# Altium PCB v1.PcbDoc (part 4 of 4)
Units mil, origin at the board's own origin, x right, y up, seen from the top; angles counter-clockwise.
Board outline 4875 x 2022 mil, 4 copper layers (Top Layer, Signal Layer 1, Signal Layer 2, Bottom Layer), stack 64.834 mil thick; 432 components, 288 nets, 1177 pads, 637 vias.
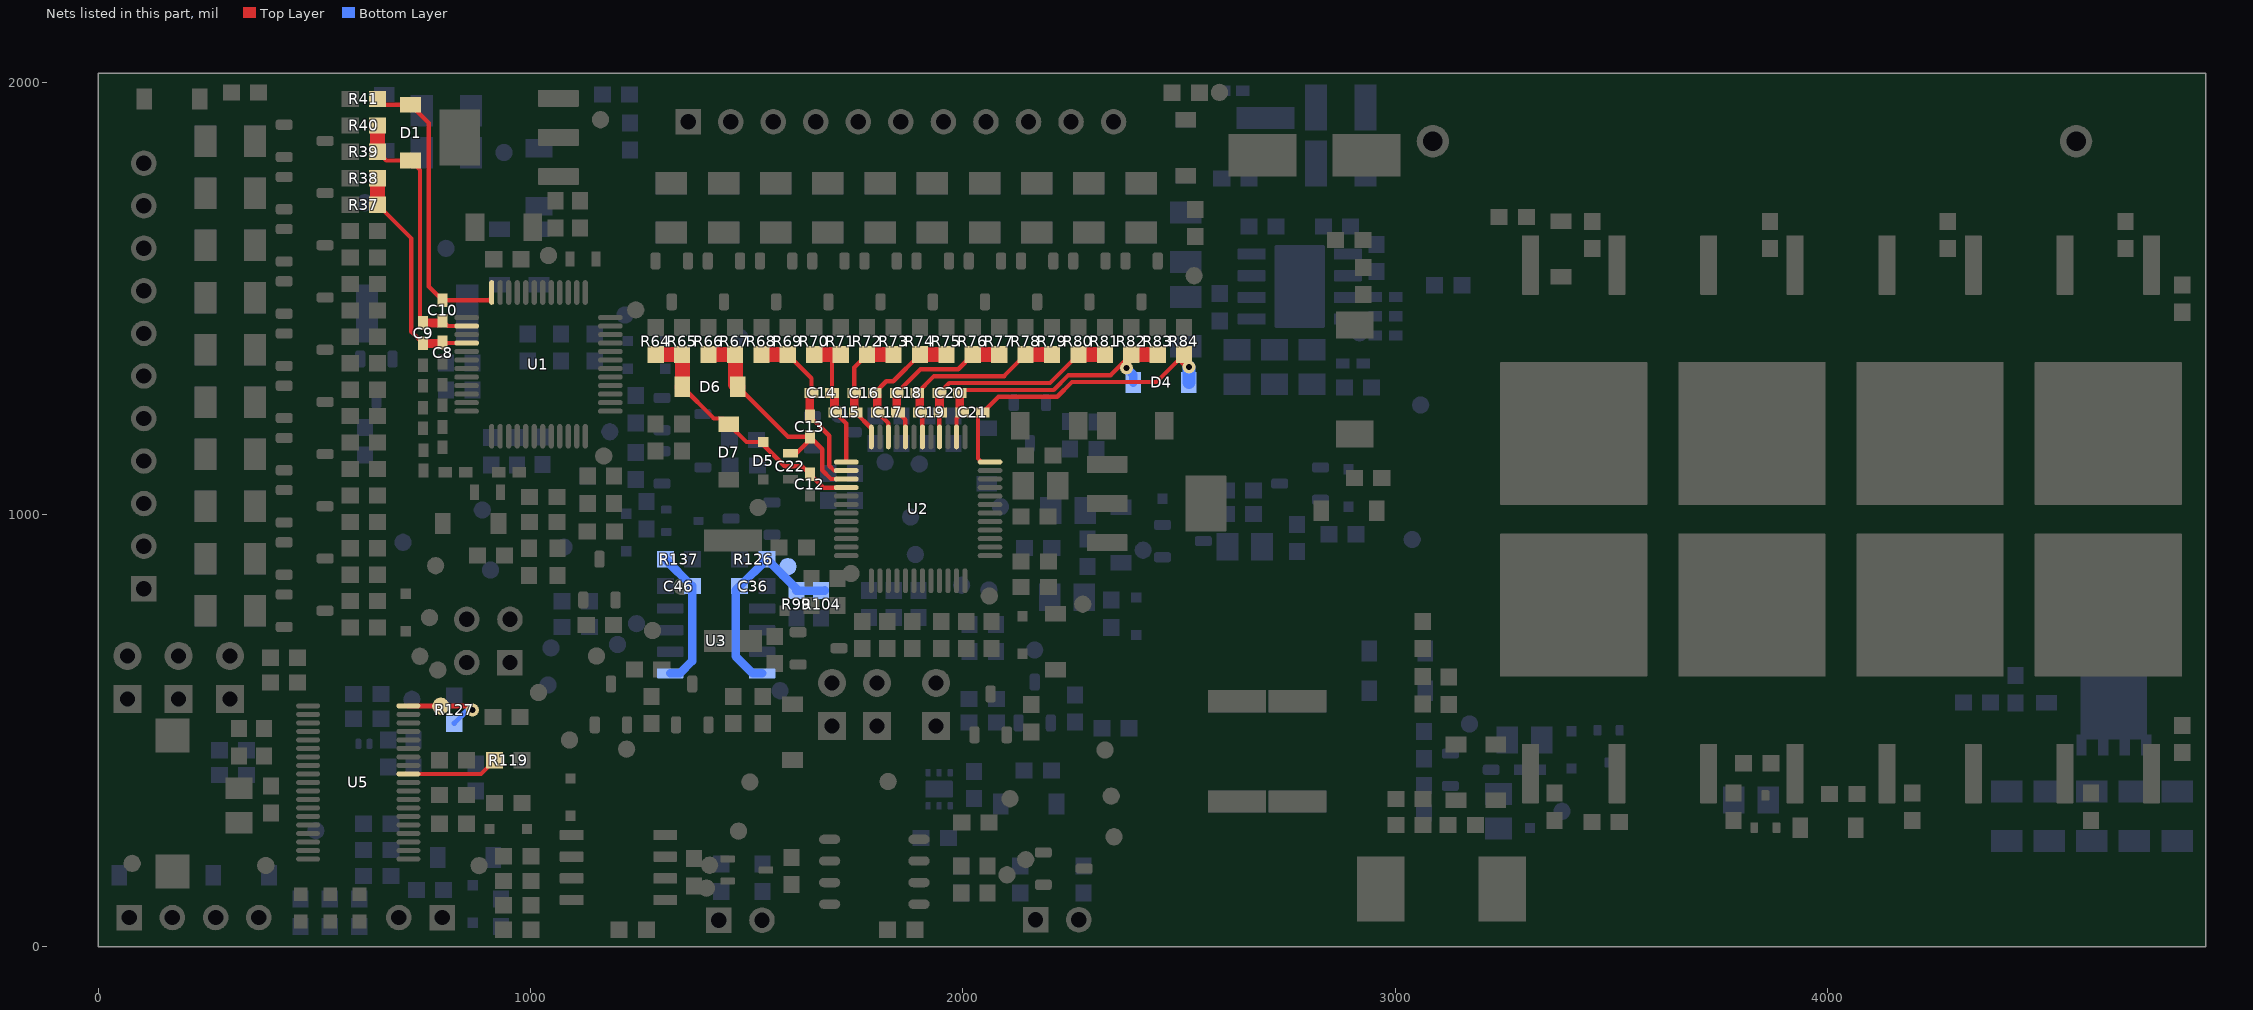
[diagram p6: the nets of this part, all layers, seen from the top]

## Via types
v1: diameter 30, hole 14, Top Layer to Bottom Layer, 615 vias
v2: diameter 19.68, hole 7.87, Top Layer to Bottom Layer, 18 vias
v3: diameter 19.68, hole 7.87, Top Layer to Bottom Layer, tented both sides, 4 vias

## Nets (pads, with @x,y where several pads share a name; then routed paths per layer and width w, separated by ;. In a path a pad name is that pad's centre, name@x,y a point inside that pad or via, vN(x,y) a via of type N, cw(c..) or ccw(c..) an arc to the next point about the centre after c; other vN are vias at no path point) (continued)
VC8: C8.1 C9.2 R37.2 R38.2 U1.4 | length 528.1
  Top Layer w10: R37.2@645.5,1717.52 724,1639.02 724,1423.38 C9.2@751,1396.38 ; C8.1@796,1398.5 797.28,1397.21 U1.4@851.66,1397.21
  Top Layer w20: C9.2@751,1396.38 793.88,1396.38 C8.1@796,1398.5
  Top Layer w35: R37.2@645.5,1717.4 645.5,1717.52 R38.2@645.5,1778.55
VC9: C9.1 C10.2 D1.2 R39.2 R40.2 U1.2 | length 642
  Top Layer w10: R39.2@645.5,1839.7 665.66,1819.53 D1.2@722,1819.53 744,1797.53 744,1450.62 C9.1@751,1443.62 ; C10.2@796,1449 808.42,1436.58 U1.2@851.66,1436.58
  Top Layer w20: C9.1@751,1443.62 790.62,1443.62 C10.2@796,1449
  Top Layer w35: R39.2@645.5,1839.7 R40.2@645.5,1900.85
VC10: C10.1 D1.1 R41.2 U1.48 | length 693
  Top Layer w10: R41.2@645.5,1962 659.03,1948.47 D1.1@722,1948.47 764,1906.47 764,1528.24 C10.1@796,1496.24 903.24,1496.24 909.73,1502.73 U1.48@909.73,1514.34
VC10B: C12.1 D5.1 D6.2 D7.1 R64.2 R65.2 U2.16 | length 615.7
  Top Layer w10: D6.2@1350.53,1296 1423.83,1222.7 1444.77,1222.7 D7.1@1458,1209.47 1499.16,1168.31 D5.1@1538,1168.31 1538,1161.94 1587.94,1112 1627.62,1112 C12.1@1646,1093.62 1676.78,1062.84 U2.16@1730.04,1062.84
  Top Layer w35: R64.2@1289.27,1370.5 R65.2@1350.39,1370.5 ; D6.2@1350.53,1296 1351.06,1296.53 R65.2@1351.06,1370.5
VC11: C13.2 C22.1 D6.1 R66.2 R67.2 U2.15 | length 570.8
  Top Layer w10: D6.1@1479.47,1296 1595.09,1180.38 C13.2@1645.88,1180.38 ; C22.1@1601,1142 1614.33,1142 1645.88,1173.55 C13.2@1645.88,1180.38 ; U2.15@1730.04,1082.53 1694.97,1082.53 1674.5,1103 1674.5,1151.76 C13.2@1645.88,1180.38
  Top Layer w35: R66.2@1411.52,1370.5 R67.2@1472.64,1370.5 1474,1369.15 1474,1301.47 D6.1@1479.47,1296
VC12: C13.1 C14.2 R68.2 R69.2 U2.14 | length 405.1
  Top Layer w10: R69.2@1594.9,1370.5 1649.76,1315.64 C14.2@1649.76,1282 ; C13.1@1645.88,1227.62 1690.5,1183 1690.5,1113.47 1701.75,1102.21 U2.14@1730.04,1102.21
  Top Layer w20: C13.1@1646,1227.62 1646,1278.24 C14.2@1649.76,1282
  Top Layer w35: R68.2@1533.77,1370.5 R69.2@1594.9,1370.5
VC13: C14.1 C15.2 R70.2 R71.2 U2.13 | length 303.3
  Top Layer w10: C14.1@1697,1282 1697,1370.5 ; C15.2@1704.38,1236.7 1730.04,1211.04 U2.13@1730.04,1121.9
  Top Layer w20: C14.1@1697,1282 1702.76,1276.24 1702.76,1238.32 C15.2@1704.38,1236.7
  Top Layer w35: R70.2@1656.02,1370.5 1697,1370.5
VC14: C15.1 C16.2 R72.2 R73.2 U2.12 | length 280.5
  Top Layer w10: C16.2@1748.42,1282 1748.42,1340.65 R72.2@1778.28,1370.5 ; C15.1@1751.62,1236.7 1788.11,1200.21 U2.12@1788.11,1179.97
  Top Layer w20: C16.2@1748.42,1282 1748.42,1239.9 C15.1@1751.62,1236.7
  Top Layer w35: R72.2@1778.28,1370.5 R73.2@1839.4,1370.5
VC15: C16.1 C17.2 R74.2 R75.2 U2.10 | length 317.9
  Top Layer w10: C16.1@1795.67,1282 1822.67,1309 1839.02,1309 R74.2@1900.53,1370.5 ; C17.2@1802.5,1236.7 1827.48,1211.72 U2.10@1827.48,1179.97
  Top Layer w20: C16.1@1795.67,1282 1801.59,1276.08 1801.59,1237.62 C17.2@1802.5,1236.7
  Top Layer w35: R74.2@1900.53,1370.5 R75.2@1961.65,1370.5
VC16: C17.1 C18.2 R76.2 R77.2 U2.8 | length 383.7
  Top Layer w10: C18.2@1847.09,1282 1901.9,1336.81 1989.09,1336.81 R76.2@2022.78,1370.5 ; C17.1@1849.75,1236.7 1866.85,1219.6 U2.8@1866.85,1179.97
  Top Layer w20: C18.2@1847.09,1282 1847.09,1239.36 C17.1@1849.75,1236.7
  Top Layer w35: R76.2@2022.78,1370.5 R77.2@2083.91,1370.5
VC17: C18.1 C19.2 R78.2 R79.2 U2.6 | length 455.4
  Top Layer w10: C18.1@1894.33,1282 1933.14,1320.81 2095.34,1320.81 R78.2@2145.03,1370.5 ; C19.2@1900.63,1236.7 1906.22,1231.11 U2.6@1906.22,1179.97
  Top Layer w20: C18.1@1894.33,1282 1900,1276.33 1900,1237.33 C19.2@1900.63,1236.7
  Top Layer w35: R78.2@2145.03,1370.5 R79.2@2206.16,1370.5
VC18: C19.1 C20.2 R80.2 R81.2 U2.4 | length 523.2
  Top Layer w10: U2.4@1945.59,1179.97 1945.59,1234.42 C19.1@1947.87,1236.7 ; C20.2@1945.76,1282 1968.57,1304.81 2201.59,1304.81 R80.2@2267.29,1370.5
  Top Layer w20: C20.2@1945.76,1282 1945.76,1238.82 C19.1@1947.87,1236.7
  Top Layer w35: R80.2@2267.29,1370.5 R81.2@2328.41,1370.5
VC19: C20.1 C21.2 D4.2 R82.2 R83.2 U2.2 | length 649.1
  Top Layer w10: U2.2@1984.96,1179.97 1984.96,1222.91 C21.2@1998.76,1236.7 ; C20.1@1993,1282 1993,1288.81 2210.03,1288.81 2244.22,1323 2342.03,1323 R82.2@2389.54,1370.5
  Top Layer w20: C20.1@1993,1282 1993,1242.46 C21.2@1998.76,1236.7
  Top Layer w35: R82.2@2389.54,1370.5 R83.2@2450.66,1370.5
  Bottom Layer w20: v1(2378,1340) 2394,1324 D4.2@2394,1306
VC20: C21.1 D4.1 R84.2 U2.48 | length 732.7
  Top Layer w10: U2.48@2062.72,1121.9 2043.1,1121.9 2035,1130 2035,1225.7 C21.1@2046,1236.7 2082.11,1272.81 2218.14,1272.81 2252.33,1307 2447.76,1307 R84.2@2511.27,1370.5
  Top Layer w20: R84.2@2511.27,1370.5 2511.27,1354.07 v1(2523.33,1342)
  Bottom Layer w30: D4.1@2522.94,1306 2523.33,1306.39 v1(2523.33,1342)
VCC1: C36.1 pad.1@1595,880 R99.2 R104.2 R126.2 U3.8 | length 498.8
  Bottom Layer w20: U3.8@1535.3,633 1513.46,633 1474,672.46 1474,825.43 C36.1@1483.5,834.93 1484.36,834.93 R126.2@1546.5,897.07 1615,828.56 R99.2@1615,824.5 R104.2@1672,824.5 1679.73,824.5 R104.2@1680,824.76
VCC1_C: R119.1 U5.30 | length 212.5
  Top Layer w10: U5.30@717.14,400.33 884.84,400.33 R119.1@916.5,432
VCC2: C46.1 R137.2 U3.1 | length 323.6
  Bottom Layer w20: R137.2@1311.5,897 1373.36,835.14 1373.36,661.42 1344.94,633 U3.1@1322.7,633
VCC2_C: pad.1@792,557 R127.1 U5.38 | length 206.6
  Top Layer w12: U5.38@717.14,557.81 855.19,557.81 v1(865,548)
  Bottom Layer w12: R127.1@823,517.5 853.5,548 v1(865,548)
pads on no net: RT7.1S RT7.2S U1.1 U1.3 U1.5 U1.7 U1.9 U1.11 U1.19 U1.39 U1.40 U1.43 U1.44 U1.45 U2.1 U2.3 U2.5 U2.7 U2.9 U2.11 U2.19 U2.40 U2.44 U4.7@1927.28,365 U4.7@1962.72,365 U5.2 U5.6 U5.12 U5.32 U5.33 U5.37 U9.6 U9.9@2779.33,1528

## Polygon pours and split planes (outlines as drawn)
NetD19_1 on Top Layer "TOP_LAYER_NETD19_1_P269" (solid, remove dead copper, pour order 269): 3046,1498 3046,512 4852,512 4852,1418.43 4211.07,1418.43 4131.5,1498
Current+ on Top Layer "TOP_LAYER_CURRENT+_P268" (solid, remove dead copper, pour order 268): 2427,488 3022,488 3022,865 2427,865
UP_GND on Top Layer "TOP_LAYER_UP_GND_P244" (solid, remove dead copper, pour order 244): 1196,2008 1196,1570 1275,1491 1275,1329 1332,1272 1401,1203 1401,619.89 1646.2,619.89 1646.2,478 1974,478 1974,616 2252.33,616 2252.33,1146.47 2381,1146.47 2381,1268 2567,1268 2567,2008
GND on Top Layer "TOP_LAYER_GND_P242" (solid, remove dead copper, pour order 242): 30,2008 30,17 2409.97,17 2409.97,885 3013,885 3013,2007 2577,2007 2577,1038 2270,1038 2270,605 1979.12,605 1979.12,463 1636,463 1636,599 1384,599 1384,1210 1264,1330 1264,1486 1186,1564 1186,2008
NetC57_2 on Top Layer "TOP_LAYER_NETC57_2_P218" (solid, remove dead copper, pour order 218): 4157,2008 3046,2008 3046,1508 4136.04,1508 4217.04,1427 4853,1427 4853,1675 4212,1675 cw(c4212,1730) 4157,1730
TOP_REG2 on Top Layer "TOP_LAYER_TOP_REG2_P190" (solid, remove dead copper, pour order 190): 1394,874.88 1528,874.88 1528,675 1394,675
NetC44_1 on Top Layer "TOP_LAYER_NETC44_1_P188" (solid, remove dead copper, pour order 188): 780,2007 998,2007 998,1944 ccw(c1016,1944) 1016,1926 1105,1926 1132,1899 1132,1820 1017,1820 ccw(c1017,1804) 1001,1804 1001,1743 780,1743
NetQ40_5 on Top Layer "TOP_LAYER_NETQ40_5_P082" (solid, remove dead copper, pour order 82): 4792,492 4792,532 cw(c4802,532) 4802,542 4833,542 4833,615 4573,615 4573,492
BAT+ on Top Layer "TOP_LAYER_BAT+_P076" (solid, remove dead copper, pour order 76): 4196,1717 4196,2008 4860,2008 4860,1717
PACK+ on Top Layer "TOP_LAYER_PACK+_P072" (solid, remove dead copper, pour order 72): 4860,17 3046,17 3046,473 4860,473
UP_GND on Bottom Layer "BOTTOM_LAYER_UP_GND_P260" (solid, remove dead copper, pour order 260): 1196,2008 1196,1570 1275,1491 1275,1329 1332,1272 1401,1203 1401,619.89 1646.2,619.89 1646.2,478 1974,478 1974,616 2248,616 2248,1063 2381,1063 2381,1268 2567,1268 2567,2008
NetC78_1 on Bottom Layer "BOTTOM_LAYER_NETC78_1_P262" (solid, remove dead copper, pour order 262): 2602.83,1327 2912,1327 2912,1271 2950,1233 2950,1209 2865,1209 2816,1258 2602.83,1258
NetD19_1 on Bottom Layer "BOTTOM_LAYER_NETD19_1_P084" (solid, remove dead copper, pour order 84): 4860,523 3095,523 3095,1496.4 4860,1496.4
NetC45_1 on Bottom Layer "BOTTOM_LAYER_NETC45_1_P266" (solid, remove dead copper, pour order 266): 2565,1416 2565,1364 2494,1364 2494,1277 2525.23,1245.77 2812.74,1245.77 2860,1198.51 2860,1157.4 2493.67,1157.4 2425,1226.07 2425,1416
GND on Bottom Layer "BOTTOM_LAYER_GND_P256" (solid, remove dead copper, pour order 256): 30,2008 30,17 2409.97,17 2409.97,885 3013,885 3013,2007 2577,2007 2577,1038 2270,1038 2270,605 1979.12,605 1979.12,463 1636,463 1636,599 1389,599 1389,1205 1264,1330 1264,1486 1186,1564 1186,2008
NetD11_1 on Bottom Layer "BOTTOM_LAYER_NETD11_1_P254" (solid, remove dead copper, pour order 254): 632,1976 632,1746 775,1746 775,1976
NetC44_1 on Bottom Layer "BOTTOM_LAYER_NETC44_1_P232" (solid, remove dead copper, pour order 232): 784,1976 784,1746 1184,1746 1184,1976
NetC57_2 on Bottom Layer "BOTTOM_LAYER_NETC57_2_P222" (solid, remove dead copper, pour order 222): 4157,2007 4157,1727.23 4157,1563 3046,1563 3046,2007
BAT+ on Bottom Layer "BOTTOM_LAYER_BAT+_P208" (solid, remove dead copper, pour order 208): 4196,1716 4196,2007 4860,2007 4860,1716
NetC77_2 on Bottom Layer "BOTTOM_LAYER_NETC77_2_P092" (solid, remove dead copper, pour order 92): 2857.33,1590 2921.95,1590 2936.95,1605 2975.33,1605 2975.33,1686 2877.33,1686 2877.33,1649 2857.33,1629
NetC72_1 on Bottom Layer "BOTTOM_LAYER_NETC72_1_P090" (solid, remove dead copper, pour order 90): 2631.33,1759 2842.33,1759 2842.33,1865 2631.33,1865
NetC71_1 on Bottom Layer "BOTTOM_LAYER_NETC71_1_P088" (solid, remove dead copper, pour order 88): 2631.33,1995 2842.33,1995 2842.33,1889 2631.33,1889
PACK+ on Bottom Layer "BOTTOM_LAYER_PACK+_P086" (solid, remove dead copper, pour order 86): 4860,275.21 4860,17 3046,17 3046,275.21
NetQ40_5 on Bottom Layer "BOTTOM_LAYER_NETQ40_5_P070" (solid, remove dead copper, pour order 70): 3547,314 3547,533 4531,533 ccw(c4531,547) 4545,547 4545,630 4860,630 4860,314
NetC45_1 on Signal Layer 2 "SIGNAL_LAYER_2_NETC45_1_P252" (solid, remove dead copper, pour order 252): 2392,1063 2689.98,1063 2689.98,1238 2392,1238
UP_GND on Signal Layer 2 "SIGNAL_LAYER_2_UP_GND_P250" (solid, remove dead copper, pour order 250): 1196,2008 1196,1570 1275,1491 1275,1329 1332,1272 1401,1203 1401,619.89 1646.2,619.89 1646.2,478 1974,478 1974,616 2244.8,616 2244.8,1063 2381,1063 2381,1249 2567,1249 2567,2008
GND on Signal Layer 2 "SIGNAL_LAYER_2_GND_P248" (solid, remove dead copper, pour order 248): 30,2008 30,17 2409.97,17 2409.97,885 3013,885 3013,2007 2577,2007 2577,1052 2256,1052 2256,605 1987,605 1987,463 1636,463 1636,599 1389,599 1389,1205 1264,1330 1264,1486 1186,1564 1186,2008
NetC44_1 on Signal Layer 2 "SIGNAL_LAYER_2_NETC44_1_P228" (solid, remove dead copper, pour order 228): 780,2007 780,1743 1132,1743 1132,2007
NetC57_2 on Signal Layer 2 "SIGNAL_LAYER_2_NETC57_2_P220" (solid, remove dead copper, pour order 220): 4157,2007 4157,1727.23 ccw(c4213.98,1731.98) 4218.73,1675 4860,1675 4860,1508 3046,1508 3046,2007
BAT+ on Signal Layer 2 "SIGNAL_LAYER_2_BAT+_P206" (solid, remove dead copper, pour order 206): 4196,1717 4196,2007 4860,2007 4860,1717
NetQ40_5 on Signal Layer 2 "SIGNAL_LAYER_2_NETQ40_5_P202" (solid, remove dead copper, pour order 202): 3046,286 3046,533 4531,533 ccw(c4531,547) 4545,547 4545,630 4860,630 4860,286
PACK+ on Signal Layer 2 "SIGNAL_LAYER_2_PACK+_P198" (solid, remove dead copper, pour order 198): 4860,266 4860,17 3046,17 3046,266 3919,266
NetD19_1 on Signal Layer 2 "SIGNAL_LAYER_2_NETD19_1_P094" (solid, remove dead copper, pour order 94): 4860,530 3046,530 3046,1498 4860,1498
GND on Signal Layer 1 "SIGNAL_LAYER_1_GND_P246" (solid, remove dead copper, pour order 246): 30,2008 30,17 2409.97,17 2409.97,885 3013,885 3013,2007 2577,2007 2577,1052 2256,1052 2256,605 1979.12,605 1979.12,463 1636,463 1636,599 1389,599 1389,1205 1264,1330 1264,1486 1186,1564 1186,2008
UP_GND on Signal Layer 1 "SIGNAL_LAYER_1_UP_GND_P240" (solid, remove dead copper, pour order 240): 1196,2008 1196,1570 1275,1491 1275,1329 1332,1272 1401,1203 1401,619.89 1646.2,619.89 1646.2,478 1974,478 1974,616 2244.8,616 2244.8,1063 2381,1063 2381,1249 2567,1249 2567,2008
NetC45_1 on Signal Layer 1 "SIGNAL_LAYER_1_NETC45_1_P234" (solid, remove dead copper, pour order 234): 2392,1063 2689.98,1063 2689.98,1238 2392,1238
NetC44_1 on Signal Layer 1 "SIGNAL_LAYER_1_NETC44_1_P226" (solid, remove dead copper, pour order 226): 780,2007 780,1743 1132,1743 1132,2007
NetC57_2 on Signal Layer 1 "SIGNAL_LAYER_1_NETC57_2_P210" (solid, remove dead copper, pour order 210): 4157,2007 4157,1727.23 ccw(c4213.98,1731.98) 4218.73,1675 4860,1675 4860,1508 3046,1508 3046,2007
BAT+ on Signal Layer 1 "SIGNAL_LAYER_1_BAT+_P204" (solid, remove dead copper, pour order 204): 4196,1717 4196,2007 4860,2007 4860,1717
NetQ40_5 on Signal Layer 1 "SIGNAL_LAYER_1_NETQ40_5_P200" (solid, remove dead copper, pour order 200): 3046,286 3046,533 4531,533 ccw(c4531,547) 4545,547 4545,630 4860,630 4860,286
PACK+ on Signal Layer 1 "SIGNAL_LAYER_1_PACK+_P196" (solid, remove dead copper, pour order 196): 4860,266 4860,17 3046,17 3046,266
NetD19_1 on Signal Layer 1 "SIGNAL_LAYER_1_NETD19_1_P096" (solid, remove dead copper, pour order 96): 4860,541 3046,541 3046,1498 4860,1498

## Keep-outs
Keep-Out Layer:
  text ".Layer_Name" at 577,-858.49 h60

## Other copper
Top Layer:
  rectangle net PACK-: 2492,17 2897,237
  rectangle net PACK+: 4194,17 4860,194
  region net BAT+: 4860,2008 4606,2008 4606,1717.18 4860,1717.18
  rectangle net Current+: 2476,690 2881,865
  rectangle net CANL: 2080,17 2197,93
  region net CANH: 2356,93 2239,93 2239,17 2356,17
  region net 485B: 1623,92 1506,92 1506,17 1623,17
  rectangle net 485A: 1347,17 1464,92
  region net NetC45_1: 2284,979 2375,979 cw(c2375,955) 2399,955 2399,919.05 2690,919.05 2690,1238 2407,1238 2407,1110 cw(c2370,1110) 2370,1073 2284,1073
  region net NetC73_1: 2590,1881.64 2590,1782.59 2772.2,1782.59 2772.2,1881.64
  region net Cell1: 143,854.19 143,741 315.91,741 315.91,854.19
  region net Cell2: 189,974.94 189,861.84 315.91,861.84 315.91,974.94
  region net Cell3: 169,1095.7 169,982.6 315.91,982.6 315.91,1095.7
  region net Cell4: 150,1216.46 150,1103.35 315.91,1103.35 315.91,1216.46
  region net Cell5: 150,1337.22 150,1224.11 315.91,1224.11 315.91,1337.22
  region net Cell6: 150,1457.98 150,1344.87 315.91,1344.87 315.91,1457.98
  region net Cell7: 150,1578.74 150,1465.63 315.91,1465.63 315.91,1578.74
  region net Cell8: 150,1699.5 150,1586.39 315.91,1586.39 315.91,1699.5
  region net Cell10: 91,1930 91,1827.91 315.91,1827.91 315.91,1930
  region net Cell9: 150,1820.25 150,1707.15 315.91,1707.15 315.91,1820.25
  region net Cell11: 1401.97,1870 1288.86,1870 1288.86,1699.09 1401.97,1699.09
  region net Cell12: 1522.72,1824 1409.62,1824 1409.62,1699.09 1522.72,1699.09
  region net Cell13: 1643.48,1842 1530.38,1842 1530.38,1699.09 1643.48,1699.09
  region net Cell14: 1764.24,1865 1651.13,1865 1651.13,1699.09 1764.24,1699.09
  region net Cell19: 2368.03,1865 2254.93,1865 2254.93,1699.09 2368.03,1699.09
  region net Cell20: 2485,1876 2375.69,1876 2375.69,1699.09 2485,1699.09
  region net Cell18: 2247.28,1865 2134.17,1865 2134.17,1699.09 2247.28,1699.09
  region net Cell17: 2126.52,1865 2013.41,1865 2013.41,1699.09 2126.52,1699.09
  region net Cell16: 2005.76,1865 1892.65,1865 1892.65,1699.09 2005.76,1699.09
  region net Cell15: 1885,1865 1771.89,1865 1771.89,1699.09 1885,1699.09
  region net NetC78_1: 2863,1252 2950.7,1252 2950.7,1155 2863,1155
  region net PACK-: 2427,413 3022,413 3022,17 2427,17
  text ".Layer_Name" at 577,-858.49 h60
Signal Layer 1:
  region net PACK-: 2428,413 3022,413 3022,17 2428,17
  region net Current+: 2428,488 3022,488 3022,865 2428,865
Signal Layer 2:
  region net PACK-: 2428,413 3022,413 3022,17 2428,17
  region net Current+: 2428,488 3022,488 3022,865 2428,865
Bottom Layer:
  rectangle net PACK+: 4194,17 4860,194
  rectangle net PACK-: 2492,17 2897,237
  rectangle net Current+: 2476,690 2884,836
  region net BAT+: 4860,2007 4586,2007 4586,1716 4860,1716
  region net NetR108_2: 2565,1424 2463,1424 2463,1666 2565,1666
  region net NetD12_1: 2463,1881 2565,1881 2565,1674 2463,1674
  region net Cell15: 1845.21,1839 1733.03,1839 1733.03,1699 1845.21,1699
  region net Cell11: 1362.17,1870 1258.59,1870 1258.59,1699 1362.17,1699
  region net Cell12: 1482.93,1816 1370.76,1816 1370.76,1699 1482.93,1699
  region net Cell13: 1603.69,1809 1491.52,1809 1491.52,1699 1603.69,1699
  region net Cell14: 1724.45,1829 1612.28,1829 1612.28,1699 1724.45,1699
  region net Cell16: 1965.97,1864.54 1853.79,1864.54 1853.79,1699 1965.97,1699
  region net Cell17: 2086.72,1875.67 1974.55,1875.67 1974.55,1699 2086.72,1699
  region net Cell18: 2207.48,1876 2095.31,1876 2095.31,1699 2207.48,1699
  region net Cell19: 2328.24,1876 2216.07,1876 2216.07,1699 2328.24,1699
  region net Cell20: 2449,1875.67 2336.83,1875.67 2336.83,1699 2449,1699
  region net NetQ20_3: 2449,1460.31 2336.83,1460.31 2336.83,1679 2449,1679
  region net NetQ19_3: 2328.24,1460.31 2216.07,1460.31 2216.07,1679 2328.24,1679
  region net NetQ18_3: 2207.48,1460.31 2095.31,1460.31 2095.31,1679 2207.48,1679
  region net NetQ17_3: 2086.72,1460.31 1974.55,1460.31 1974.55,1679 2086.72,1679
  region net NetQ16_3: 1965.97,1460.31 1853.79,1460.31 1853.79,1679 1965.97,1679
  region net NetQ15_3: 1845.21,1460.31 1733.03,1460.31 1733.03,1679 1845.21,1679
  region net NetQ14_3: 1724.45,1460.31 1612.28,1460.31 1612.28,1679 1724.45,1679
  region net NetQ13_3: 1603.69,1460.31 1491.52,1460.31 1491.52,1679 1603.69,1679
  region net NetQ12_3: 1482.93,1460.31 1370.76,1460.31 1370.76,1679 1482.93,1679
  region net NetQ11_3: 1362.17,1460.31 1258.59,1460.31 1258.59,1679 1362.17,1679
  region net NetQ1_3: 622,741.03 622,855.03 336,855.03 336,741.03
  region net NetQ2_3: 622,861.79 622,975.79 336,975.79 336,861.79
  region net NetQ3_3: 600,982.55 600,1096.55 336,1096.55 336,982.55
  region net NetQ4_3: 585,1103.31 585,1217.31 336,1217.31 336,1103.31
  region net NetQ5_3: 585,1224.07 585,1338.07 336,1338.07 336,1224.07
  region net NetQ6_3: 585,1344.82 585,1458.82 336,1458.82 336,1344.82
  region net NetQ7_3: 588,1465.58 588,1579.58 336,1579.58 336,1465.58
  region net NetQ8_3: 588,1586.34 588,1700.34 336,1700.34 336,1586.34
  region net NetQ9_3: 588,1707.1 588,1821.1 336,1821.1 336,1707.1
  region net NetQ10_3: 588,1827.86 588,1941.86 336,1941.86 336,1827.86
  region net Cell1: 154,855.03 154,741.03 322.8,741.03 322.8,855.03
  region net Cell2: 209,975.79 209,861.79 322.8,861.79 322.8,975.79
  region net Cell3: 187,1096.55 187,982.55 322.8,982.55 322.8,1096.55
  region net Cell4: 167,1217.31 167,1103.31 322.8,1103.31 322.8,1217.31
  region net Cell5: 154,1338.07 154,1224.07 322.8,1224.07 322.8,1338.07
  region net Cell6: 154,1458.82 154,1344.82 322.8,1344.82 322.8,1458.82
  region net Cell7: 154,1579.58 154,1465.58 322.8,1465.58 322.8,1579.58
  region net Cell8: 154,1700.34 154,1586.34 322.8,1586.34 322.8,1700.34
  region net Cell9: 154,1821.1 154,1707.1 322.8,1707.1 322.8,1821.1
  region net Cell10: 149,1941.86 149,1827.86 322.8,1827.86 322.8,1941.86
  region net PACK-: 2428,413 3022,413 3022,17 2428,17
  region net Current+: 2428,488 3022,488 3022,865 2428,865
  region net NetC76_2: 2970.33,1471.31 2857.33,1471.31 2857.33,1403 2970.33,1403
  region net BOT_REG2: 879,1399 879,1532 742,1532 742,1399
  region net NetQ26_3: 595,1533 595,1400 732,1400 732,1533
  text ".Layer_Name" at 577,-858.49 h60

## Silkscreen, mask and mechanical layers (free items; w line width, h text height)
Top Overlay:
  text "BAT+" at 4527,1945 h72.83
  text "REGIN" at 1144,1869.48 h30
  text "TOPBAT" at 2507,1507 h30
  text "BotReg1" at 1160.7,1499 h30
  text "REG18" at 1154.5,1167.48 h30
  text "TOPWAKE" at 1306,889.19 h30 r270
  text "BAT-" at 2801.77,877.59 h72.83
  text "BOTCB" at 748,839 h30
  text "SDA" at 838,816 h72.83
  text "REGIN" at 2266,748 h30
  text "DOFF" at 1297.02,696.51 h30
  text "COFF" at 1057.37,666.06 h30
  text "SDA" at 662.98,652.07 h30
  text "SCL" at 705.98,620.3 h30
  text "BotWa" at 1042,594 h30
  text "VCC2" at 760,513 h30
  text "TopWa" at 1039,506 h30
  text "MCU reset" at 74,431 h30 r270
  text "5V" at 2270,417 h30
  text "VCC1" at 1191,408 h30
  text "PowEn" at 2142.8,347 h30
  text "TopShut" at 1761.8,339.53 h30
  text "TopAle" at 1495,339 h30
  text "DMosOff" at 2301,294 h30
  text "PACK-" at 2430.2,255 h72.83 r270
  text "PACK+" at 4306.96,230.01 h72.83
  text "SBIO" at 248.91,128.71 h60
  text "3V3" at 37,128 h60
  text "DET" at 715.81,125.9 h72.83
  text "A" at 1302,39.57 h72.83
  text "L" at 2032.04,37 h72.83
  text "H" at 2373,37 h72.83
  text "B" at 1633.26,34.71 h72.83
  text ".Layer_Name" at 577,-858.49 h60
Bottom Overlay:
  text "BOTBAT" at 665,1671.1 h30
  text "BOTPACK" at 1311.37,1492.26 h30
  text "BOTLD" at 1542.25,1364 h30
  text "CHG" at 3060.5,1200.91 h30
  text "BREG1" at 1172,1148.82 h30
  text "TDOF" at 1977,1074 h30
  text "TCOF" at 1853.79,1065 h30
  text "TOPDCHG" at 1957,1022 h30
  text "PDSG" at 3066.5,974.73 h30
  text "TOPDSG" at 2153.89,974 h30
  text "BOTSHUT" at 915,964 h30
  text "TOPDDSG" at 1949,931 h30
  text "BOTCB" at 725.3,883.79 h30
  text "BOTDDSG" at 1108.87,878 h30
  text "VCC1" at 1694.19,870.76 h30
  text "VCC2" at 880.75,838.72 h30
  text "BOTALERT" at 771,667 h30 r90
  text "Current+" at 1094,655 h30
  text "SDA" at 1225,647.49 h30
  text "Current-" at 1081,555.5 h30
  text "DSG" at 3204,544 h30
  text "TOPREG2" at 1625,542.74 h30
  text ".Layer_Name" at 577,-858.49 h60
Top Paste:
  text ".Layer_Name" at 577,-858.49 h60
Bottom Paste:
  rectangle: 3154,602 4351,991
  rectangle: 3154,766 4840,1476
  text ".Layer_Name" at 577,-858.49 h60
Top Solder:
  text ".Layer_Name" at 577,-858.49 h60
  text ".Layer_Name" at 577,-858.49 h60
Bottom Solder:
  rectangle: 3154,602 4351,991
  rectangle: 3154,766 4840,1476
  text ".Layer_Name" at 577,-858.49 h60
Drill Guide:
  text ".Layer_Name" at 577,-858.49 h60
M1 Board Outline:
  the board outline again, w10
  text ".Layer_Name" at 577,-858.49 h60
M2 Board Dimensions:
  rectangle: 0,-275 125,-150
  rectangle: 125,-400 500,-275
  lines w7: 0,-275 1000,-275 ; 125,-400 125,-150 ; 250,-400 250,-150 ; 500,-400 500,-150 ; 750,-400 750,-150 ; 0,-400 1000,-400 1000,-150 0,-150 0,-400
  text ".Layer_Name" at 577,-858.49 h60
M3 3D STEP Top:
  text ".Layer_Name" at 577,-858.49 h60
M4 3D STEP Bottom:
  text ".Layer_Name" at 577,-858.49 h60
M5 Assembly Top:
  lines w10: -292,-930.17 6308,-930.17 ; -292,-726.83 6310,-726.83 ; -292,-523.5 -292,-1133.5 3713,-1133.5 6310,-1133.5 6310,-523.5 -291.5,-523.5 -291.5,-1133.5 1284,-1133.5 ; 2173,-1133.5 2173,-523.5 ; 3440,-726.83 3440,-523.5 ; 4280,-726.83 4280,-523.5 ; 4902,-1140 4902,-937.17
  text "COMPONENTS MARKED 'DNP' SHOULD NOT BE POPULATED." at 1153.5,-318.5 h60
  text "ASSEMBLY VARIANT:" at 1153,-434 h60
  text ".VariantName" at 2189,-434 h60
  text "PCB VIEWED FROM TOP SIDE" at -228.5,-655.67 h60
  text "BOARD #:" at 2248,-655.67 h60
  text ".PRJ_Number" at 2793.5,-655.67 h60
  text "REV:" at 3638,-655.67 h60
  text ".PCB_Rev" at 3929.5,-655.67 h60
  text "SVN REV:" at 4476,-655.67 h60
  text ".VersionControl_RevNumber" at 4982,-655.67 h60
  text "TID #:" at 2248,-859 h60
  text ".TID" at 2793.5,-859 h60
  text "PLOT NAME =" at -228.5,-1064.34 h60
  text ".plot_File_Name" at 577,-1064.34 h60
  text "GENERATED    :" at 2250,-1064.34 h60
  text ".Print_Date" at 3119.5,-1064.34 h60
  text ".Print_Time" at 3848.5,-1064.34 h60
  text "TEXAS INSTRUMENTS" at 5113,-1064.34 h60
M6 Assembly Bottom:
  lines w10: -292.5,-727.33 6309.5,-727.33 ; -290.5,-930.67 6309.5,-930.67 ; 1115.5,-1140.5 1115.5,-937.67 ; 1737.5,-727.33 1737.5,-524 ; 2577.5,-727.33 2577.5,-524 ; 3844.5,-1134 3844.5,-524 ; 4733.5,-1134 6309,-1134 6309,-524 -292.5,-524 -292.5,-1134 2304.5,-1134 6309.5,-1134 6309.5,-524
  text "COMPONENTS MARKED 'DNP' SHOULD NOT BE POPULATED." at 6102,-318 h60
  text ".VariantName" at 5058,-434 h60
  text "ASSEMBLY VARIANT:" at 6097,-434 h60
  text ".VersionControl_RevNumber" at 1035.5,-656.17 h60
  text "SVN REV:" at 1541.5,-656.17 h60
  text ".PCB_Rev" at 2088,-656.17 h60
  text "REV:" at 2379.5,-656.17 h60
  text ".PRJ_Number" at 3224,-656.17 h60
  text "BOARD #:" at 3769.5,-656.17 h60
  text "PCB VIEWED FROM BOTTOM SIDE" at 6246,-656.17 h60
  text ".TID" at 3224,-859.5 h60
  text "TID #:" at 3769.5,-859.5 h60
  text "TEXAS INSTRUMENTS" at 904.5,-1064.84 h60
  text ".Print_Time" at 2169,-1064.84 h60
  text ".Print_Date" at 2898,-1064.84 h60
  text "GENERATED    :" at 3767.5,-1064.84 h60
  text ".plot_File_Name" at 5440.5,-1064.84 h60
  text "PLOT NAME =" at 6246,-1064.84 h60
M9 Title Sheet:
  drawing of 57 lines, arcs and shapes, not listed
  text "1" at 739.84,8036.5 h70
  text "2" at 3235.5,8036.5 h70
  text "3" at 5724.84,8036.5 h70
  text "4" at 8231.51,8036.5 h70
  text "5" at 10730.5,8036.5 h70
  text "6" at 13235.5,8036.5 h70
  text "A" at -416.5,6893.5 h70
  text "A" at 14383.5,6893.5 h70
  text "B" at -416.5,4513.5 h70
  text "B" at 14383.5,4513.5 h70
  text "C" at -416.5,2138.5 h70
  text "C" at 14383.5,2138.5 h70
  text "PROJECT TITLE:" at 11343.5,277.5 h45
  text ".PRJ_Title" at 11393.5,144.17 h70
  text "DESIGNED FOR:" at 11343.5,-23.5 h45
  text ".PRJ_Customer" at 11393.5,-163.5 h70
  text "D" at -416.5,-231.5 h70
  text "D" at 14383.5,-231.5 h70
  text "FILE NAME:" at 11343.5,-323.5 h45
  text ".PCB_File_Name_No_Path" at 11393.5,-443.5 h70
  text "Texas Instruments (TI) and/or its licensors do not warrant the accuracy or completeness of this specification" at 6374,-605.34 h45
  text "ENGINEER:" at 11343.5,-613.5 h45
  text "LAYOUT BY:" at 12848.5,-613.5 h45
  text "or any information contained therein. TI and/or its licensors do not warrant that this design will meet" at 6329.01,-718 h45
  text ".PRJ_Engineer" at 11393.5,-768.49 h70
  text ".PCB_Layout" at 12899,-768.49 h70
  text "the specifications, will be suitable for your application or fit for any particular purpose, or will operate in" at 6329.01,-830.67 h45
  text ".Layer_Name" at 577,-858.49 h60
  text "ALTIUM DESIGNER VERSION:" at 12848.5,-923.5 h45
  text "an implementation. TI and/or its licensors do not warrant that the design is production worthy. You should" at 6329.01,-943.33 h45
  text "completely validate and test your design implementation to confirm the system functionality for your application." at 6374,-1056 h45
  text ".print_Scale" at 11393.5,-1056.83 h70
  text ".Application_BuildNumber" at 12899,-1056.83 h70
  text "1" at 739.84,-1263.5 h70
  text "2" at 3235.5,-1263.5 h70
  text "3" at 5724.84,-1263.5 h70
  text "4" at 8231.51,-1263.5 h70
  text "5" at 10730.5,-1263.5 h70
  text "6" at 13235.5,-1263.5 h70
M10 Fab Notes:
  drawing of 189 lines, arcs and shapes, not listed
  text "DESIGN INFORMATION" at 12382.02,6356.17 h60
  text "MIN. TRACK WIDTH:" at 11737.46,6224.05 h60
  text "8" at 12833.7,6224.05 h60
  text "MIL" at 12988.46,6224.05 h60
  text "MIN. CLEARANCE:" at 11737.46,6099.92 h60
  text "0.2" at 12773.7,6099.93 h60
  text "mm" at 12988.46,6099.92 h60
  text "MIN. VIA PAD SIZE:" at 11737.46,5975.8 h60
  text "24" at 12803.71,5975.8 h60
  text "MIL" at 12988.46,5975.8 h60
  text "0.05mm (2MIL)" at 12432.46,5845.9 h60
  text "MINIMUM ANNULAR RING" at 11408.23,5837.67 h60
  text "EXTERNAL" at 13140.46,5837.67 h60
  text "PER" at 11608.23,5727.55 h60
  text "IPC-D-275 CLASS 2 LEVEL C" at 11828.23,5727.54 h60
  text "MIL, HOLES" at 13316.46,5627.07 h60
  text "+/-" at 12924,5618.48 h60
  text "+/-" at 13778,5618.48 h60
  text "REGISTRATION TOLERANCES:" at 11408.23,5617.42 h60
  text "METAL" at 12608,5617.42 h60
  text "5" at 13184.2,5617.42 h60
  text "3" at 14017.2,5617.42 h60
  text "MIL" at 14133.46,5617.42 h60
  text "HOLE SIZE TOLERANCE (UNLESS OTHERWISE SPECIFIED):" at 11408.23,5519.1 h60
  text "+/-" at 13778,5516.23 h60
  text "3" at 14017.2,5515.17 h60
  text "MIL" at 14133.46,5515.17 h60
  text "MATERIAL:" at 11333.46,5377.52 h60
  text "FR-4 High Tg" at 12319.9,5249 h60
  text "X" at 12175.46,5241.01 h60
  text "FR-408" at 11754.46,5236.49 h60
  text "OTHER" at 13242.46,5236.49 h60
  text "62 MIL (1.6mm) +/-10%" at 12074.56,5093.46 h60
  text "X" at 11954.46,5091.01 h60
  text "THICKNESS:" at 11408.23,5085.24 h60
  text "OTHER" at 13359.46,5085.24 h60
  text "TOLERANCE:" at 11408.23,4946.92 h60
  text "X" at 12256.46,4946.92 h60
  text "ANSI IPC-6012 TYPE 3 CLASS 2" at 12434.48,4946.92 h60
  text "OTHER +/-" at 12434.46,4802.73 h60
  text "BOW & TWIST:" at 11408.23,4657.54 h60
  text "X" at 12256.46,4657.54 h60
  text "ANSI IPC-6012 TYPE 3 CLASS 2" at 12434.48,4657.54 h60
  text "OTHER +/-" at 12434.46,4510.85 h60
  text "DRILLING:" at 11333.46,4380.23 h60
  text "NC_DRILL FILES" at 13094.46,4275.04 h60
  text "REFERENCE:" at 11408.23,4271.1 h60
  text "X" at 12065.46,4271.01 h60
  text "AS SHOWN" at 12243.46,4271.1 h60
  text "X" at 12966.46,4271.1 h60
  text "OTHER" at 13392.46,4128.85 h60
  text "PTH COPPER THICKNESS:" at 11407.91,4125.32 h60
  text "X" at 12547.14,4125.32 h60
  text "20-30 um" at 12675.14,4125.32 h60
  text "BOARD FINISH:" at 11333.46,3977.73 h60
  text "SILKSCREEN:" at 11488.68,3867.6 h60
  text "X" at 12446.46,3867.6 h60
  text "TOP" at 12563.46,3867.6 h60
  text "X" at 12956.46,3867.6 h60
  text "BOTTOM" at 13074.46,3867.6 h60
  text "SILKSCREEN COLOR:" at 11488.68,3712.41 h60
  text "X" at 12445.46,3712.41 h60
  text "WHITE" at 12563.46,3712.41 h60
  text "OTHER" at 13074.46,3712.41 h60
  text "X" at 12576.46,3568.96 h60
  text "GREEN" at 12694.46,3568.96 h60
  text "OTHER" at 13312.46,3568.96 h60
  text "SOLDER RESIST COLOR:" at 11488.68,3562.1 h60
  text "X" at 12576.46,3414.71 h60
  text "MATTE" at 12694.46,3414.71 h60
  text "SEMI-GLOSS" at 13312,3414.07 h60
  text "IMMERSION GOLD (ENIG)" at 12394.46,3241.94 h60
  text "ENEPIG" at 13732,3234.72 h60
  text "SURFACE FINISH:" at 11333.46,3233.72 h60
  text "X" at 12216.46,3233.72 h60
  text "IMM. TIN/SILVER OR EQUIV" at 11663,3096.4 h60
  text "OTHER" at 13094.46,3092.47 h60
  text "ARRAY/PANEL:" at 11333.46,2937.09 h60
  text "CUT AND TRIM PER M1 BOARD OUTLINE" at 12394.46,2928.87 h60
  text "N.C. ROUTE" at 12394.46,2792.9 h60
  text "X" at 13082.46,2792.9 h60
  text "V. SCORE" at 13260.46,2792.9 h60
  text "CERTIFICATION:" at 11333.46,2663.77 h60
  text "MATERIALS AND WORKMANSHIP FOR ALL PCBS" at 12058.46,2663.77 h60
  text "TO MEET OR EXCEED THE REQUIREMENTS OF:" at 12058.46,2569.71 h60
  text "X" at 11695.97,2441.08 h60
  text "ANSI IPC-A-600F CLASS ->" at 11823.96,2441.08 h60
  text "X" at 13471.97,2441.08 h60
  text "2" at 13581.96,2441.08 h60
  text "1" at 13266.96,2439.58 h60
  text "3" at 13935.96,2439.58 h60
  text "X" at 12507.97,2293.39 h60
  text "RoHS" at 12635.96,2293.39 h60
  text "OTHER" at 13280.36,2293.39 h60
  text "PER ORDER" at 13677.42,2293.39 h60
  text "ALL BOARDS MUST MEET OR EXCEED UL94-V0 REQUIREMENTS." at 11361,2139.57 h60
  text "PCB MUST BEAR THE UL94V-0 UL REGISTERED MATERIAL ID NUMBER" at 11361,2023.5 h60
  text "ADDITIONAL REQUIREMENTS:" at 11333.46,1854.08 h60
  text "MICROSECTION:" at 11408.23,1746.95 h60
  text "YES" at 12313.96,1746.95 h60
  text "REQUIRED" at 13175.46,1602.62 h60
  text "BARE BOARD ELEC. TEST:" at 11408.23,1599.76 h60
  text "NONE" at 12713.96,1599.76 h60
  text "X" at 13057.46,1599.76 h60
  text "PER ORDER" at 13767.46,1599.76 h60
  text "XX MIL VIAS REQUIRE NON-CONDUCTIVE FILL AND PLANARIZE" at 11576.38,1394.82 h59
  text "XX MIL VIAS REQUIRE CONDUCTIVE FILL AND PLANARIZE" at 11584.38,1290.84 h60
  text "OUTER XX MIL TRACES REQUIRE 50 OHM SINGLE-ENDED IMPEDANCE" at 11583.39,1127.46 h58
  text "LAYER 2 & 3 (INNER LAYERS) XX MIL WIDE, XX MIL SPACE / TRACES REQUIRE 100 OHM DIFFERENTIAL IMPEDANCE" at 11575.39,891.74 h60
  text ".Layer_Name" at 577,-858.49 h60
M11 Gerber Information:
  lines w10: -292,-930.17 6308,-930.17 ; -292,-726.83 6310,-726.83 ; -292,-523.5 -292,-1133.5 3713,-1133.5 6310,-1133.5 6310,-523.5 -291.5,-523.5 -291.5,-1133.5 1284,-1133.5 ; 2173,-1133.5 2173,-523.5 ; 3440,-726.83 3440,-523.5 ; 4280,-726.83 4280,-523.5 ; 4902,-1140 4902,-937.17
  text "ALL ARTWORK VIEWED FROM TOP SIDE" at -228.5,-655.67 h60
  text "BOARD #:" at 2248,-655.67 h60
  text ".PRJ_Number" at 2793.5,-655.67 h60
  text "REV:" at 3638,-655.67 h60
  text ".PCB_Rev" at 3929.5,-655.67 h60
  text "SVN REV:" at 4476,-655.67 h60
  text ".VersionControl_RevNumber" at 4982,-655.67 h60
  text "LAYER NAME =" at -228.5,-858.49 h60
  text "TID #:" at 2248,-859 h60
  text ".TID" at 2793.5,-859 h60
  text "PLOT NAME =" at -228.5,-1064.34 h60
  text ".plot_File_Name" at 577,-1064.34 h60
  text "GENERATED    :" at 2250,-1064.34 h60
  text ".Print_Date" at 3119.5,-1064.34 h60
  text ".Print_Time" at 3848.5,-1064.34 h60
  text "TEXAS INSTRUMENTS" at 5113,-1064.34 h60
M12 Stackup:
  drawing of 624 lines, arcs and shapes, not listed
  text "Layer" at 9797.84,7830 h60
  text "Name" at 10207.76,7830 h60
  text "Material" at 11137.5,7830 h60
  text "Thickness" at 11997.27,7830 h60
  text "Constant" at 12647.1,7830 h60
  text "Board Layer Stack" at 13216.96,7830 h60
  text "1" at 9797.84,7710 h60
  text "Top Overlay" at 10207.76,7710 h60
  text "2" at 9797.84,7590 h60
  text "Top Solder" at 10207.76,7590 h60
  text "Solder Resist" at 11137.5,7590 h60
  text "0.40mil" at 11997.27,7590 h60
  text "3.5" at 12647.1,7590 h60
  text "3" at 9797.84,7470 h60
  text "Top Layer" at 10207.76,7470 h60
  text "Copper" at 11137.5,7470 h60
  text "1.40mil" at 11997.27,7470 h60
  text "4" at 9797.84,7350 h60
  text "Dielectric1" at 10207.76,7350 h60
  text "FR-4" at 11137.5,7350 h60
  text "59.20mil" at 11997.27,7350 h60
  text "4.8" at 12647.1,7350 h60
  text "5" at 9797.84,7230 h60
  text "Bottom Layer" at 10207.76,7230 h60
  text "Copper" at 11137.5,7230 h60
  text "1.40mil" at 11997.27,7230 h60
  text "6" at 9797.84,7110 h60
  text "Bottom Solder" at 10207.76,7110 h60
  text "Solder Resist" at 11137.5,7110 h60
  text "0.40mil" at 11997.27,7110 h60
  text "3.5" at 12647.1,7110 h60
  text "7" at 9797.84,6990 h60
  text "Bottom Overlay" at 10207.76,6990 h60
  text "Layer" at 9807.84,6885 h60
  text "Name" at 10217.76,6885 h60
  text "Material" at 11157.5,6885 h60
  text "Thickness" at 12017.26,6885 h60
  text "Constant" at 12667.1,6885 h60
  text "Board Layer Stack" at 13236.96,6885 h60
  text "Board Layer Stack" at 14356.64,6885 h60
  text "Top Overlay" at 10217.76,6765 h60
  text "Top Solder" at 10217.76,6645 h60
  text "Solder Resist" at 11157.5,6645 h60
  text "0.40mil" at 12017.26,6645 h60
  text "3.5" at 12667.1,6645 h60
  text "1" at 9807.84,6525 h60
  text "Top Layer" at 10217.76,6525 h60
  text "1.40mil" at 12017.26,6525 h60
  text "Dielectric1" at 10217.76,6405 h60
  text "FR-4" at 11157.5,6405 h60
  text "59.20mil" at 12017.26,6405 h60
  text "4.8" at 12667.1,6405 h60
  text "2" at 9807.84,6285 h60
  text "Signal Layer 1" at 10217.76,6285 h60
  text "1.42mil" at 12017.26,6285 h60
  text "3" at 9807.84,6165 h60
  text "Signal Layer 2" at 10217.76,6165 h60
  text "1.42mil" at 12017.26,6165 h60
  text "4" at 9807.84,6045 h60
  text "Bottom Layer" at 10217.76,6045 h60
  text "1.40mil" at 12017.26,6045 h60
  text "Bottom Solder" at 10217.76,5925 h60
  text "Solder Resist" at 11157.5,5925 h60
  text "0.40mil" at 12017.26,5925 h60
  text "3.5" at 12667.1,5925 h60
  text "Bottom Overlay" at 10217.76,5805 h60
  text ".Layer_Name" at 577,-858.49 h60
M13 Component Bodies Top:
  text ".Layer_Name" at 577,-858.49 h60
M14 Component Bodies Bottom:
  text ".Layer_Name" at 577,-858.49 h60
M15 Courtyards Top:
  text ".Layer_Name" at 577,-858.49 h60
M16 Courtyards Bottom:
  text ".Layer_Name" at 577,-858.49 h60
Drill Drawing:
  text ".Layer_Name" at 577,-858.49 h60
M17 Embedded Cavity:
  text ".Layer_Name" at 577,-858.49 h60
M18 Embedded Assembly:
  text ".Layer_Name" at 577,-858.49 h60
M19 Embedded Keepout:
  text ".Layer_Name" at 577,-858.49 h60

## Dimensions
0,0 to 0,2022 on M2 Board Dimensions
0,-400 to 1000,-400 on M2 Board Dimensions
0,0 to 4875,2022 on M2 Board Dimensions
